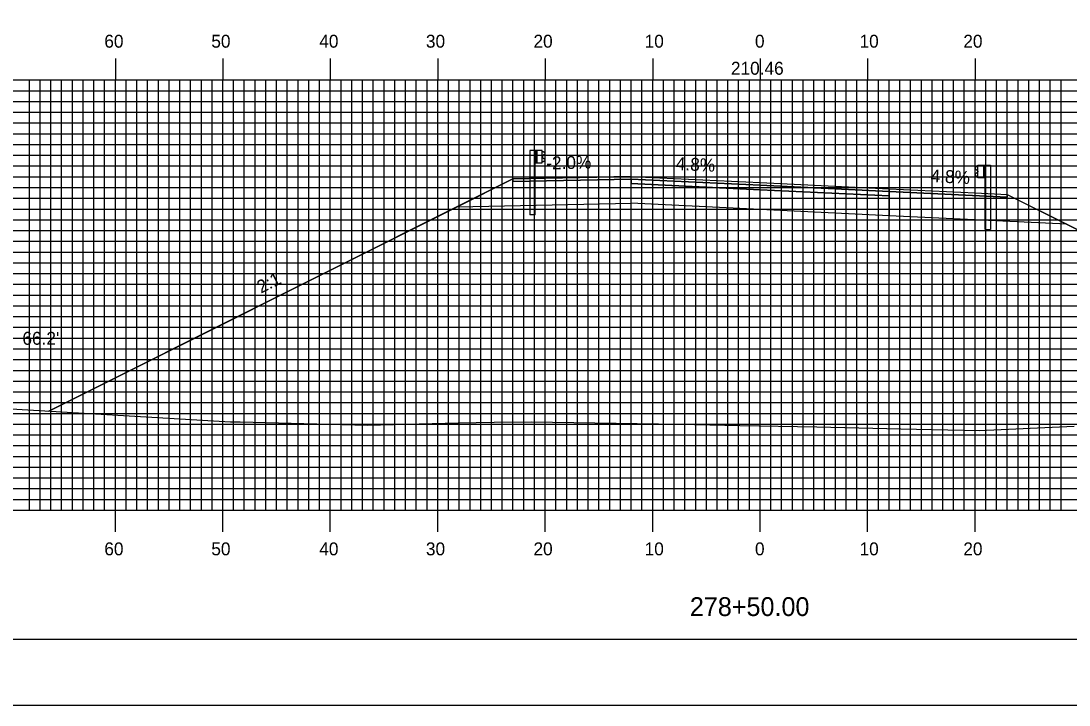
# Model space of a CAD drawing. Extents: x 1810587 to 1810930, y 442591 to 442811.
# Drawn here: x 1810683.6 to 1810781.1, y 442590.5 to 442654.1 of the extents above; entities that cross this region are included whole.
import ezdxf

# ---------------------------------------------------------------- set-up
doc = ezdxf.new("R2010")
doc.units = 0
for name, color, linetype in [('ANNOTATION', 7, 'Continuous'), ('BORDER', 7, 'Continuous'), ('D_Guardrail_Beam_Lt', 7, 'Continuous'), ('D_Guardrail_Beam_Rt', 7, 'Continuous'), ('D_Roadway_Centerline', 7, 'Continuous'), ('D_Roadway_Centerline_Text', 7, 'Continuous'), ('D_Roadway_Edge_Shoulder', 7, 'Continuous'), ('D_Roadway_Edge_TW', 7, 'Continuous'), ('D_Roadway_Pavement', 7, 'Continuous'), ('D_Roadway_SlopeLines', 7, 'Continuous'), ('D_Roadway_SubGrade', 7, 'Continuous'), ('D_Text_Standard', 7, 'Continuous'), ('H_V ANNOTATION', 7, 'Continuous'), ('MAJOR', 7, 'Continuous'), ('MINOR', 7, 'Continuous'), ('PLOT BOUNDARY', 7, 'Continuous'), ('S_Roadway_Centerline', 7, 'Continuous')]:
    doc.layers.add(name, color=color, linetype=linetype)

msp = doc.modelspace()

# ---------------------------------------------------------------- linework, layer by layer
at = {"layer": 'BORDER'}
msp.add_lwpolyline([(1810602.777, 442596.665), (1810922.777, 442596.665), (1810922.777, 442806.665), (1810602.777, 442806.665)], close=True, dxfattribs=at)
at = {"layer": 'D_Guardrail_Beam_Lt'}
for p, q in [((1810730.947, 442642.12), (1810730.947, 442636.12)), ((1810731.418, 442642.12), (1810730.947, 442642.12)), ((1810732.106, 442642.12), (1810731.418, 442642.12)), ((1810731.418, 442642.12), (1810731.418, 442640.953)), ((1810731.481, 442642.12), (1810731.481, 442640.953)), ((1810731.585, 442642.12), (1810731.585, 442640.953)), ((1810732.106, 442640.953), (1810732.106, 442642.12)), ((1810732.106, 442642.036), (1810732.18, 442642.022)), ((1810732.11, 442641.571), (1810732.11, 442641.501)), ((1810732.339, 442641.772), (1810732.144, 442641.636)), ((1810732.144, 442641.437), (1810732.339, 442641.301)), ((1810732.196, 442642.015), (1810732.339, 442641.915)), ((1810731.418, 442640.953), (1810732.106, 442640.953)), ((1810731.439, 442636.12), (1810731.439, 442640.953)), ((1810732.18, 442641.051), (1810732.106, 442641.036)), ((1810732.339, 442641.157), (1810732.196, 442641.057)), ((1810731.439, 442636.12), (1810730.947, 442636.12))]:
    msp.add_line(p, q, dxfattribs=at)
for centre, major_axis, start_param, end_param in [((1810732.189, 442641.571), (-0.0789, 0), 5.323254, 6.283185), ((1810732.189, 442641.501), (-0.0789, 0), 6.283185, 7.243116), ((1810732.172, 442641.981), (0.0417, 0), 0.959931, 1.376053), ((1810732.289, 442641.843), (0.0877, 0), 5.323254, 7.243116), ((1810732.172, 442641.091), (0.0417, 0), 4.907132, 5.323254), ((1810732.289, 442641.229), (0.0877, 0), 5.323254, 7.243116)]:
    msp.add_ellipse(centre, major_axis=major_axis, ratio=0.995501, start_param=start_param, end_param=end_param, dxfattribs=at)
at = {"layer": 'D_Guardrail_Beam_Rt'}
for p, q in [((1810772.557, 442640.639), (1810772.414, 442640.539)), ((1810772.647, 442640.66), (1810772.573, 442640.646)), ((1810772.647, 442640.744), (1810773.335, 442640.744)), ((1810772.647, 442639.577), (1810772.647, 442640.744)), ((1810773.168, 442640.744), (1810773.168, 442639.577)), ((1810773.272, 442640.744), (1810773.272, 442639.577)), ((1810773.335, 442640.744), (1810773.806, 442640.744)), ((1810773.335, 442640.744), (1810773.335, 442639.577)), ((1810773.806, 442640.744), (1810773.806, 442634.744)), ((1810772.414, 442640.396), (1810772.609, 442640.26)), ((1810772.609, 442640.061), (1810772.414, 442639.925)), ((1810772.414, 442639.781), (1810772.557, 442639.681)), ((1810772.573, 442639.675), (1810772.647, 442639.66)), ((1810772.643, 442640.195), (1810772.643, 442640.125)), ((1810773.335, 442639.577), (1810772.647, 442639.577)), ((1810773.314, 442634.744), (1810773.314, 442639.577)), ((1810773.314, 442634.744), (1810773.806, 442634.744))]:
    msp.add_line(p, q, dxfattribs=at)
for centre, major_axis, start_param, end_param in [((1810772.464, 442640.467), (-0.0877, 0), 5.323254, 7.243116), ((1810772.581, 442640.605), (-0.0417, 0), 4.907132, 5.323254), ((1810772.464, 442639.853), (-0.0877, 0), 5.323254, 7.243116), ((1810772.581, 442639.715), (-0.0417, 0), 0.959931, 1.376053), ((1810772.564, 442640.195), (0.0789, 0), 0, 0.959931), ((1810772.564, 442640.125), (0.0789, 0), 5.323254, 6.283185)]:
    msp.add_ellipse(centre, major_axis=major_axis, ratio=0.995501, start_param=start_param, end_param=end_param, dxfattribs=at)
at = {"layer": 'D_Roadway_Centerline'}
msp.add_lwpolyline([(1810686.18, 442617.878), (1810724.168, 442636.872), (1810729.377, 442639.476), (1810732.377, 442639.536), (1810740.377, 442639.696), (1810752.377, 442639.12), (1810764.377, 442638.544), (1810772.377, 442638.16), (1810775.377, 442638.016), (1810780.908, 442635.251), (1810819.863, 442615.773)], dxfattribs=at)
at = {"layer": 'D_Roadway_Edge_Shoulder'}
for points in [[(1810740.377, 442639.696), (1810732.377, 442639.536), (1810732.377, 442639.536), (1810729.377, 442639.476), (1810729.377, 442639.226), (1810740.377, 442639.446)], [(1810764.377, 442638.544), (1810772.377, 442638.16), (1810772.377, 442638.16), (1810775.377, 442638.016), (1810775.377, 442637.766), (1810764.377, 442638.294)]]:
    msp.add_lwpolyline(points, close=True, dxfattribs=at)
at = {"layer": 'D_Roadway_Edge_TW'}
msp.add_lwpolyline([(1810740.377, 442639.446), (1810740.377, 442639.696), (1810752.377, 442639.12), (1810764.377, 442638.544), (1810764.377, 442638.294), (1810752.377, 442638.87)], close=True, dxfattribs=at)
at = {"layer": 'D_Roadway_Pavement'}
msp.add_lwpolyline([(1810740.377, 442639.03), (1810740.377, 442639.446), (1810752.377, 442638.87), (1810764.377, 442638.294), (1810764.377, 442637.878), (1810752.377, 442638.454)], close=True, dxfattribs=at)
for points in [[(1810740.377, 442639.446), (1810740.377, 442639.03)], [(1810764.377, 442638.294), (1810764.377, 442637.878)]]:
    msp.add_lwpolyline(points, dxfattribs=at)
at = {"layer": 'D_Roadway_SlopeLines'}
for points in [[(1810729.377, 442639.476), (1810686.18, 442617.878)], [(1810775.377, 442638.016), (1810819.863, 442615.773)]]:
    msp.add_lwpolyline(points, dxfattribs=at)
at = {"layer": 'D_Roadway_SubGrade'}
for points in [[(1810740.377, 442639.03), (1810740.377, 442639.446), (1810729.377, 442639.226), (1810729.377, 442639.476), (1810724.168, 442636.872), (1810740.377, 442637.196)], [(1810740.377, 442637.196), (1810740.377, 442639.446), (1810740.377, 442639.03), (1810752.377, 442638.454), (1810764.377, 442637.878), (1810764.377, 442638.294), (1810764.377, 442636.044), (1810752.377, 442636.62)], [(1810764.377, 442637.878), (1810764.377, 442638.294), (1810775.377, 442637.766), (1810775.377, 442638.016), (1810780.908, 442635.251), (1810764.377, 442636.044)]]:
    msp.add_lwpolyline(points, close=True, dxfattribs=at)
at = {"layer": 'MAJOR'}
for p, q in [((1810692.377, 442650.669), (1810692.377, 442648.665)), ((1810702.377, 442650.669), (1810702.377, 442648.665)), ((1810712.377, 442650.669), (1810712.377, 442648.665)), ((1810722.377, 442650.669), (1810722.377, 442648.665)), ((1810732.377, 442650.669), (1810732.377, 442648.665)), ((1810742.377, 442650.669), (1810742.377, 442648.665)), ((1810752.377, 442650.669), (1810752.377, 442648.665)), ((1810762.377, 442650.669), (1810762.377, 442648.665)), ((1810772.377, 442650.669), (1810772.377, 442648.665)), ((1810612.377, 442648.665), (1810892.377, 442648.665)), ((1810612.377, 442648.665), (1810892.377, 442648.665)), ((1810692.377, 442608.665), (1810692.377, 442648.665)), ((1810702.377, 442608.665), (1810702.377, 442648.665)), ((1810712.377, 442608.665), (1810712.377, 442648.665)), ((1810722.377, 442608.665), (1810722.377, 442648.665)), ((1810732.377, 442608.665), (1810732.377, 442648.665)), ((1810742.377, 442608.665), (1810742.377, 442648.665)), ((1810752.377, 442608.665), (1810752.377, 442648.665)), ((1810762.377, 442608.665), (1810762.377, 442648.665)), ((1810772.377, 442608.665), (1810772.377, 442648.665)), ((1810612.377, 442643.665), (1810892.377, 442643.665)), ((1810612.377, 442638.665), (1810892.377, 442638.665)), ((1810612.377, 442633.665), (1810892.377, 442633.665)), ((1810612.377, 442628.665), (1810892.377, 442628.665)), ((1810612.377, 442623.665), (1810892.377, 442623.665)), ((1810612.377, 442618.665), (1810892.377, 442618.665)), ((1810612.377, 442613.665), (1810892.377, 442613.665)), ((1810612.377, 442608.665), (1810892.377, 442608.665)), ((1810612.377, 442608.665), (1810892.377, 442608.665)), ((1810692.377, 442606.661), (1810692.377, 442608.665)), ((1810702.377, 442606.661), (1810702.377, 442608.665)), ((1810712.377, 442606.661), (1810712.377, 442608.665)), ((1810722.377, 442606.661), (1810722.377, 442608.665)), ((1810732.377, 442606.661), (1810732.377, 442608.665)), ((1810742.377, 442606.661), (1810742.377, 442608.665)), ((1810752.377, 442606.661), (1810752.377, 442608.665)), ((1810762.377, 442606.661), (1810762.377, 442608.665)), ((1810772.377, 442606.661), (1810772.377, 442608.665))]:
    msp.add_line(p, q, dxfattribs=at)
at = {"layer": 'MINOR'}
for p, q in [((1810684.377, 442608.665), (1810684.377, 442648.665)), ((1810685.377, 442608.665), (1810685.377, 442648.665)), ((1810686.377, 442608.665), (1810686.377, 442648.665)), ((1810687.377, 442608.665), (1810687.377, 442648.665)), ((1810688.377, 442608.665), (1810688.377, 442648.665)), ((1810689.377, 442608.665), (1810689.377, 442648.665)), ((1810690.377, 442608.665), (1810690.377, 442648.665)), ((1810691.377, 442608.665), (1810691.377, 442648.665)), ((1810693.377, 442608.665), (1810693.377, 442648.665)), ((1810694.377, 442608.665), (1810694.377, 442648.665)), ((1810695.377, 442608.665), (1810695.377, 442648.665)), ((1810696.377, 442608.665), (1810696.377, 442648.665)), ((1810697.377, 442608.665), (1810697.377, 442648.665)), ((1810698.377, 442608.665), (1810698.377, 442648.665)), ((1810699.377, 442608.665), (1810699.377, 442648.665)), ((1810700.377, 442608.665), (1810700.377, 442648.665)), ((1810701.377, 442608.665), (1810701.377, 442648.665)), ((1810703.377, 442608.665), (1810703.377, 442648.665)), ((1810704.377, 442608.665), (1810704.377, 442648.665)), ((1810705.377, 442608.665), (1810705.377, 442648.665)), ((1810706.377, 442608.665), (1810706.377, 442648.665)), ((1810707.377, 442608.665), (1810707.377, 442648.665)), ((1810708.377, 442608.665), (1810708.377, 442648.665)), ((1810709.377, 442608.665), (1810709.377, 442648.665)), ((1810710.377, 442608.665), (1810710.377, 442648.665)), ((1810711.377, 442608.665), (1810711.377, 442648.665)), ((1810713.377, 442608.665), (1810713.377, 442648.665)), ((1810714.377, 442608.665), (1810714.377, 442648.665)), ((1810715.377, 442608.665), (1810715.377, 442648.665)), ((1810716.377, 442608.665), (1810716.377, 442648.665)), ((1810717.377, 442608.665), (1810717.377, 442648.665)), ((1810718.377, 442608.665), (1810718.377, 442648.665)), ((1810719.377, 442608.665), (1810719.377, 442648.665)), ((1810720.377, 442608.665), (1810720.377, 442648.665)), ((1810721.377, 442608.665), (1810721.377, 442648.665)), ((1810723.377, 442608.665), (1810723.377, 442648.665)), ((1810724.377, 442608.665), (1810724.377, 442648.665)), ((1810725.377, 442608.665), (1810725.377, 442648.665)), ((1810726.377, 442608.665), (1810726.377, 442648.665)), ((1810727.377, 442608.665), (1810727.377, 442648.665)), ((1810728.377, 442608.665), (1810728.377, 442648.665)), ((1810729.377, 442608.665), (1810729.377, 442648.665)), ((1810730.377, 442608.665), (1810730.377, 442648.665)), ((1810731.377, 442608.665), (1810731.377, 442648.665)), ((1810733.377, 442608.665), (1810733.377, 442648.665)), ((1810734.377, 442608.665), (1810734.377, 442648.665)), ((1810735.377, 442608.665), (1810735.377, 442648.665)), ((1810736.377, 442608.665), (1810736.377, 442648.665)), ((1810737.377, 442608.665), (1810737.377, 442648.665)), ((1810738.377, 442608.665), (1810738.377, 442648.665)), ((1810739.377, 442608.665), (1810739.377, 442648.665)), ((1810740.377, 442608.665), (1810740.377, 442648.665)), ((1810741.377, 442608.665), (1810741.377, 442648.665)), ((1810743.377, 442608.665), (1810743.377, 442648.665)), ((1810744.377, 442608.665), (1810744.377, 442648.665)), ((1810745.377, 442608.665), (1810745.377, 442648.665)), ((1810746.377, 442608.665), (1810746.377, 442648.665)), ((1810747.377, 442608.665), (1810747.377, 442648.665)), ((1810748.377, 442608.665), (1810748.377, 442648.665)), ((1810749.377, 442608.665), (1810749.377, 442648.665)), ((1810750.377, 442608.665), (1810750.377, 442648.665)), ((1810751.377, 442608.665), (1810751.377, 442648.665)), ((1810753.377, 442608.665), (1810753.377, 442648.665)), ((1810754.377, 442608.665), (1810754.377, 442648.665)), ((1810755.377, 442608.665), (1810755.377, 442648.665)), ((1810756.377, 442608.665), (1810756.377, 442648.665)), ((1810757.377, 442608.665), (1810757.377, 442648.665)), ((1810758.377, 442608.665), (1810758.377, 442648.665)), ((1810759.377, 442608.665), (1810759.377, 442648.665)), ((1810760.377, 442608.665), (1810760.377, 442648.665)), ((1810761.377, 442608.665), (1810761.377, 442648.665)), ((1810763.377, 442608.665), (1810763.377, 442648.665)), ((1810764.377, 442608.665), (1810764.377, 442648.665)), ((1810765.377, 442608.665), (1810765.377, 442648.665)), ((1810766.377, 442608.665), (1810766.377, 442648.665)), ((1810767.377, 442608.665), (1810767.377, 442648.665)), ((1810768.377, 442608.665), (1810768.377, 442648.665)), ((1810769.377, 442608.665), (1810769.377, 442648.665)), ((1810770.377, 442608.665), (1810770.377, 442648.665)), ((1810771.377, 442608.665), (1810771.377, 442648.665)), ((1810773.377, 442608.665), (1810773.377, 442648.665)), ((1810774.377, 442608.665), (1810774.377, 442648.665)), ((1810775.377, 442608.665), (1810775.377, 442648.665)), ((1810776.377, 442608.665), (1810776.377, 442648.665)), ((1810777.377, 442608.665), (1810777.377, 442648.665)), ((1810778.377, 442608.665), (1810778.377, 442648.665)), ((1810779.377, 442608.665), (1810779.377, 442648.665)), ((1810780.377, 442608.665), (1810780.377, 442648.665)), ((1810612.377, 442647.665), (1810892.377, 442647.665)), ((1810612.377, 442646.665), (1810892.377, 442646.665)), ((1810612.377, 442645.665), (1810892.377, 442645.665)), ((1810612.377, 442644.665), (1810892.377, 442644.665)), ((1810612.377, 442642.665), (1810892.377, 442642.665)), ((1810612.377, 442641.665), (1810892.377, 442641.665)), ((1810612.377, 442640.665), (1810892.377, 442640.665)), ((1810612.377, 442639.665), (1810892.377, 442639.665)), ((1810612.377, 442637.665), (1810892.377, 442637.665)), ((1810612.377, 442636.665), (1810892.377, 442636.665)), ((1810612.377, 442635.665), (1810892.377, 442635.665)), ((1810612.377, 442634.665), (1810892.377, 442634.665)), ((1810612.377, 442632.665), (1810892.377, 442632.665)), ((1810612.377, 442631.665), (1810892.377, 442631.665)), ((1810612.377, 442630.665), (1810892.377, 442630.665)), ((1810612.377, 442629.665), (1810892.377, 442629.665)), ((1810612.377, 442627.665), (1810892.377, 442627.665)), ((1810612.377, 442626.665), (1810892.377, 442626.665)), ((1810612.377, 442625.665), (1810892.377, 442625.665)), ((1810612.377, 442624.665), (1810892.377, 442624.665)), ((1810612.377, 442622.665), (1810892.377, 442622.665)), ((1810612.377, 442621.665), (1810892.377, 442621.665)), ((1810612.377, 442620.665), (1810892.377, 442620.665)), ((1810612.377, 442619.665), (1810892.377, 442619.665)), ((1810612.377, 442617.665), (1810892.377, 442617.665)), ((1810612.377, 442616.665), (1810892.377, 442616.665)), ((1810612.377, 442615.665), (1810892.377, 442615.665)), ((1810612.377, 442614.665), (1810892.377, 442614.665)), ((1810612.377, 442612.665), (1810892.377, 442612.665)), ((1810612.377, 442611.665), (1810892.377, 442611.665)), ((1810612.377, 442610.665), (1810892.377, 442610.665)), ((1810612.377, 442609.665), (1810892.377, 442609.665))]:
    msp.add_line(p, q, dxfattribs=at)
at = {"layer": 'PLOT BOUNDARY'}
msp.add_lwpolyline([(1810586.59, 442590.547), (1810926.59, 442590.547), (1810926.59, 442810.547), (1810586.59, 442810.547)], close=True, dxfattribs=at)
at = {"layer": 'S_Roadway_Centerline'}
msp.add_lwpolyline([(1810681.059, 442618.18), (1810703.103, 442616.878), (1810703.994, 442616.873), (1810705.209, 442616.849), (1810715.834, 442616.565), (1810724.283, 442616.79), (1810727.618, 442616.837), (1810731.096, 442616.866), (1810744.871, 442616.667), (1810750.502, 442616.538), (1810757.649, 442616.41), (1810765.465, 442616.223), (1810772.756, 442616.063), (1810781.608, 442616.48)], dxfattribs=at)

# ---------------------------------------------------------------- texts
at = {"layer": 'ANNOTATION'}
for s, rotation, p in [('-2.0%', 1.14576, (1810732.483, 442640.339)), ('4.8%', 357.25191, (1810744.506, 442640.3)), ('-4.8%', 357.25191, (1810767.685, 442639.188)), ('2:1', 26.56505, (1810705.923, 442628.786))]:
    msp.add_text(s, height=1.2, rotation=rotation, dxfattribs=at).set_placement(p)
at = {"layer": 'D_Roadway_Centerline'}
for s, p in [('C', (1810752.371, 442639.12)), ('L', (1810752.377, 442639.113))]:
    msp.add_text(s, height=0.0146, dxfattribs=at).set_placement(p)
at = {"layer": 'D_Roadway_Centerline_Text'}
msp.add_text('210.46', height=1.2, dxfattribs=at).set_placement((1810749.658, 442649.15))
at = {"layer": 'D_Text_Standard'}
msp.add_text("66.2'", height=1.2, dxfattribs=at).set_placement((1810683.724, 442624.044))
at = {"layer": 'H_V ANNOTATION'}
for s, height, p in [('60', 1.2, (1810691.349, 442651.665)), ('50', 1.2, (1810701.306, 442651.665)), ('40', 1.2, (1810711.349, 442651.665)), ('30', 1.2, (1810721.274, 442651.665)), ('20', 1.2, (1810731.285, 442651.665)), ('10', 1.2, (1810741.627, 442651.665)), ('0', 1.2, (1810751.895, 442651.665)), ('10', 1.2, (1810761.627, 442651.665)), ('20', 1.2, (1810771.285, 442651.665)), ('60', 1.2, (1810691.349, 442604.465)), ('50', 1.2, (1810701.306, 442604.465)), ('40', 1.2, (1810711.349, 442604.465)), ('30', 1.2, (1810721.274, 442604.465)), ('20', 1.2, (1810731.285, 442604.465)), ('10', 1.2, (1810741.627, 442604.465)), ('0', 1.2, (1810751.895, 442604.465)), ('10', 1.2, (1810761.627, 442604.465)), ('20', 1.2, (1810771.285, 442604.465)), ('278+50.00', 1.75, (1810745.837, 442598.821))]:
    msp.add_text(s, height=height, dxfattribs=at).set_placement(p)

doc.saveas('drawing.dxf')
